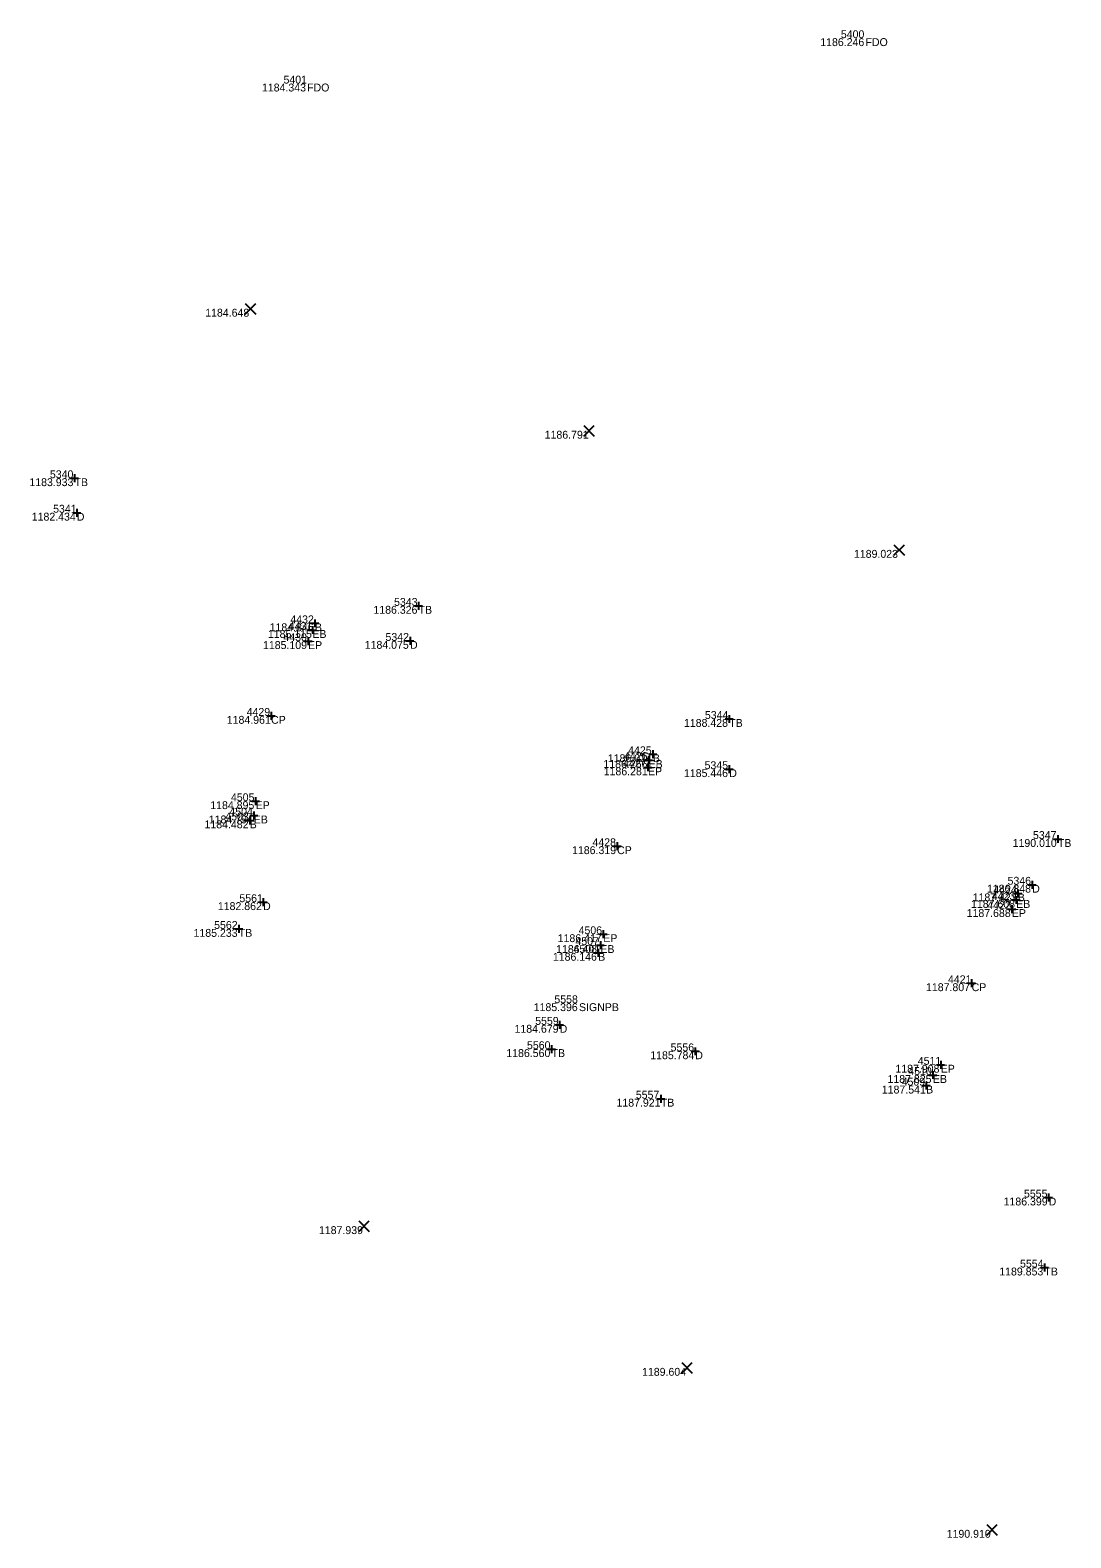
# Model space of a CAD drawing. Extents: x 2044997 to 2050342, y 455233 to 458054.
# Drawn here: x 2047059.7 to 2047191.5, y 457097.5 to 457288.5 of the extents above; entities that cross this region are included whole.
import ezdxf

# ---------------------------------------------------------------- set-up
doc = ezdxf.new("R2010")
doc.units = 0
for name, color, linetype in [('SV_X_Random_Point', 7, 'Continuous'), ('SV_X_Shot_Marker', 7, 'Continuous'), ('SV_X_Text_Comment', 7, 'Continuous'), ('SV_X_Text_Elevation', 7, 'Continuous'), ('SV_X_Text_Name', 7, 'Continuous')]:
    doc.layers.add(name, color=color, linetype=linetype)

msp = doc.modelspace()

# ---------------------------------------------------------------- linework, layer by layer
at = {"layer": 'SV_X_Random_Point'}
for p, q in [((2047086.91, 457252.54), (2047088.24, 457253.87)), ((2047086.91, 457253.87), (2047088.24, 457252.54)), ((2047129.8, 457237.08), (2047131.13, 457238.42)), ((2047129.8, 457238.42), (2047131.13, 457237.08)), ((2047169.1, 457221.99), (2047170.43, 457223.32)), ((2047169.1, 457223.32), (2047170.43, 457221.99)), ((2047101.3, 457136.31), (2047102.63, 457137.65)), ((2047101.3, 457137.65), (2047102.63, 457136.31)), ((2047142.23, 457118.36), (2047143.56, 457119.7)), ((2047142.23, 457119.7), (2047143.56, 457118.36)), ((2047180.86, 457097.84), (2047182.19, 457099.18)), ((2047180.86, 457099.18), (2047182.19, 457097.84))]:
    msp.add_line(p, q, dxfattribs=at)
at = {"layer": 'SV_X_Shot_Marker'}
for p, q in [((2047065.28, 457232.24), (2047065.28, 457231.24)), ((2047064.78, 457231.74), (2047065.78, 457231.74)), ((2047065.28, 457231.74), (2047065.28, 457231.74)), ((2047065.07, 457227.37), (2047066.07, 457227.37)), ((2047065.57, 457227.87), (2047065.57, 457226.87)), ((2047065.57, 457227.37), (2047065.57, 457227.37)), ((2047108.38, 457215.57), (2047109.38, 457215.57)), ((2047108.88, 457216.07), (2047108.88, 457215.07)), ((2047108.88, 457215.57), (2047108.88, 457215.57)), ((2047095.24, 457213.36), (2047096.24, 457213.36)), ((2047095.42, 457213.01), (2047095.42, 457212.01)), ((2047095.74, 457213.86), (2047095.74, 457212.86)), ((2047095.74, 457213.36), (2047095.74, 457213.36)), ((2047094.37, 457211.1), (2047095.37, 457211.1)), ((2047094.87, 457211.6), (2047094.87, 457210.6)), ((2047094.87, 457211.1), (2047094.87, 457211.1)), ((2047094.92, 457212.51), (2047095.92, 457212.51)), ((2047095.42, 457212.51), (2047095.42, 457212.51)), ((2047107.29, 457211.13), (2047108.29, 457211.13)), ((2047107.79, 457211.63), (2047107.79, 457210.63)), ((2047107.79, 457211.13), (2047107.79, 457211.13)), ((2047089.69, 457201.63), (2047090.69, 457201.63)), ((2047090.19, 457202.13), (2047090.19, 457201.13)), ((2047090.19, 457201.63), (2047090.19, 457201.63)), ((2047147.74, 457201.24), (2047148.74, 457201.24)), ((2047148.24, 457201.74), (2047148.24, 457200.74)), ((2047148.24, 457201.24), (2047148.24, 457201.24)), ((2047137.52, 457196.04), (2047138.52, 457196.04)), ((2047137.94, 457195.61), (2047137.94, 457194.61)), ((2047138.02, 457196.54), (2047138.02, 457195.54)), ((2047138.02, 457196.04), (2047138.02, 457196.04)), ((2047138.06, 457196.77), (2047139.06, 457196.77)), ((2047138.56, 457197.27), (2047138.56, 457196.27)), ((2047138.56, 457196.77), (2047138.56, 457196.77)), ((2047137.44, 457195.11), (2047138.44, 457195.11)), ((2047137.94, 457195.11), (2047137.94, 457195.11)), ((2047147.74, 457194.88), (2047148.74, 457194.88)), ((2047148.24, 457195.38), (2047148.24, 457194.38)), ((2047148.24, 457194.88), (2047148.24, 457194.88)), ((2047087.73, 457190.82), (2047088.73, 457190.82)), ((2047088.23, 457191.32), (2047088.23, 457190.32)), ((2047088.23, 457190.82), (2047088.23, 457190.82)), ((2047086.98, 457188.39), (2047087.98, 457188.39)), ((2047087.48, 457188.89), (2047087.48, 457187.89)), ((2047087.48, 457188.39), (2047087.48, 457188.39)), ((2047087.49, 457189.01), (2047088.49, 457189.01)), ((2047087.99, 457189.51), (2047087.99, 457188.51)), ((2047087.99, 457189.01), (2047087.99, 457189.01)), ((2047189.38, 457186.03), (2047190.38, 457186.03)), ((2047189.88, 457186.53), (2047189.88, 457185.53)), ((2047189.88, 457186.03), (2047189.88, 457186.03)), ((2047133.53, 457185.12), (2047134.53, 457185.12)), ((2047134.03, 457185.62), (2047134.03, 457184.62)), ((2047134.03, 457185.12), (2047134.03, 457185.12)), ((2047186.12, 457180.24), (2047187.12, 457180.24)), ((2047186.62, 457180.74), (2047186.62, 457179.74)), ((2047186.62, 457180.24), (2047186.62, 457180.24)), ((2047089.17, 457178.53), (2047089.17, 457177.53)), ((2047184.3, 457179.14), (2047185.3, 457179.14)), ((2047184.6, 457178.81), (2047184.6, 457177.81)), ((2047184.8, 457179.64), (2047184.8, 457178.64)), ((2047184.8, 457179.14), (2047184.8, 457179.14)), ((2047088.67, 457178.03), (2047089.67, 457178.03)), ((2047089.17, 457178.03), (2047089.17, 457178.03)), ((2047183.55, 457177.15), (2047184.55, 457177.15)), ((2047184.05, 457177.65), (2047184.05, 457176.65)), ((2047184.05, 457177.15), (2047184.05, 457177.15)), ((2047184.1, 457178.31), (2047185.1, 457178.31)), ((2047184.6, 457178.31), (2047184.6, 457178.31)), ((2047085.59, 457174.64), (2047086.59, 457174.64)), ((2047086.09, 457175.14), (2047086.09, 457174.14)), ((2047086.09, 457174.64), (2047086.09, 457174.64)), ((2047131.41, 457172.59), (2047132.41, 457172.59)), ((2047131.78, 457173.97), (2047132.78, 457173.97)), ((2047131.91, 457173.09), (2047131.91, 457172.09)), ((2047131.91, 457172.59), (2047131.91, 457172.59)), ((2047132.28, 457174.47), (2047132.28, 457173.47)), ((2047132.28, 457173.97), (2047132.28, 457173.97)), ((2047131.13, 457171.61), (2047132.13, 457171.61)), ((2047131.63, 457172.11), (2047131.63, 457171.11)), ((2047131.63, 457171.61), (2047131.63, 457171.61)), ((2047178.45, 457167.76), (2047179.45, 457167.76)), ((2047178.95, 457168.26), (2047178.95, 457167.26)), ((2047178.95, 457167.76), (2047178.95, 457167.76)), ((2047126.25, 457162.49), (2047127.25, 457162.49)), ((2047126.75, 457162.99), (2047126.75, 457161.99)), ((2047126.75, 457162.49), (2047126.75, 457162.49)), ((2047125.23, 457159.41), (2047126.23, 457159.41)), ((2047125.73, 457159.91), (2047125.73, 457158.91)), ((2047125.73, 457159.41), (2047125.73, 457159.41)), ((2047143.93, 457159.64), (2047143.93, 457158.64)), ((2047143.43, 457159.14), (2047144.43, 457159.14)), ((2047143.93, 457159.14), (2047143.93, 457159.14)), ((2047174.53, 457157.43), (2047175.53, 457157.43)), ((2047175.03, 457157.93), (2047175.03, 457156.93)), ((2047175.03, 457157.43), (2047175.03, 457157.43)), ((2047173.54, 457156.13), (2047174.54, 457156.13)), ((2047174.04, 457156.63), (2047174.04, 457155.63)), ((2047174.04, 457156.13), (2047174.04, 457156.13)), ((2047139.57, 457153.63), (2047139.57, 457152.63)), ((2047172.68, 457154.79), (2047173.68, 457154.79)), ((2047173.18, 457155.29), (2047173.18, 457154.29)), ((2047173.18, 457154.79), (2047173.18, 457154.79)), ((2047139.07, 457153.13), (2047140.07, 457153.13)), ((2047139.57, 457153.13), (2047139.57, 457153.13)), ((2047188.21, 457140.61), (2047189.21, 457140.61)), ((2047188.71, 457141.11), (2047188.71, 457140.11)), ((2047188.71, 457140.61), (2047188.71, 457140.61)), ((2047187.67, 457131.74), (2047188.67, 457131.74)), ((2047188.17, 457132.24), (2047188.17, 457131.24)), ((2047188.17, 457131.74), (2047188.17, 457131.74))]:
    msp.add_line(p, q, dxfattribs=at)

# ---------------------------------------------------------------- texts
at = {"layer": 'SV_X_Text_Comment'}
for s, p in [('FDO', (2047165.5, 457286.49)), ('FDO', (2047094.75, 457280.74)), ('TB', (2047065.28, 457230.74)), ('D', (2047065.57, 457226.37)), ('TB', (2047108.88, 457214.57)), ('B', (2047095.74, 457212.36)), ('EP', (2047094.87, 457210.1)), ('EB', (2047095.42, 457211.51)), ('D', (2047107.79, 457210.13)), ('CP', (2047090.19, 457200.63)), ('TB', (2047148.24, 457200.24)), ('EB', (2047138.02, 457195.04)), ('B', (2047138.56, 457195.77)), ('EP', (2047137.94, 457194.11)), ('D', (2047148.24, 457193.88)), ('EP', (2047088.23, 457189.82)), ('B', (2047087.48, 457187.39)), ('EB', (2047087.99, 457188.01)), ('TB', (2047189.88, 457185.03)), ('CP', (2047134.03, 457184.12)), ('D', (2047186.62, 457179.24)), ('B', (2047184.8, 457178.14)), ('D', (2047089.17, 457177.03)), ('EP', (2047184.05, 457176.15)), ('EB', (2047184.6, 457177.31)), ('TB', (2047086.09, 457173.64)), ('EB', (2047131.91, 457171.59)), ('EP', (2047132.28, 457172.97)), ('B', (2047131.63, 457170.61)), ('CP', (2047178.95, 457166.76)), ('SIGNPB', (2047129.2, 457164.23)), ('D', (2047126.75, 457161.49)), ('TB', (2047125.73, 457158.41)), ('D', (2047143.93, 457158.14)), ('EP', (2047175.03, 457156.43)), ('EB', (2047174.04, 457155.13)), ('B', (2047173.18, 457153.79)), ('TB', (2047139.57, 457152.13)), ('D', (2047188.71, 457139.61)), ('TB', (2047188.17, 457130.74))]:
    msp.add_text(s, height=1, dxfattribs=at).set_placement(p)
at = {"layer": 'SV_X_Text_Elevation'}
for s, p in [('1186.246', (2047159.77, 457286.49)), ('1184.343', (2047089.03, 457280.74)), ('1184.648', (2047081.84, 457252.21)), ('1186.791', (2047124.85, 457236.75)), ('1183.933', (2047059.56, 457230.74)), ('1182.434', (2047059.86, 457226.37)), ('1189.023', (2047164.04, 457221.66)), ('1186.326', (2047103.15, 457214.57)), ('1184.846', (2047090, 457212.36)), ('1185.109', (2047089.16, 457210.1)), ('1185.115', (2047089.78, 457211.51)), ('1184.075', (2047102.05, 457210.13)), ('1184.961', (2047084.57, 457200.63)), ('1188.428', (2047142.5, 457200.24)), ('1186.266', (2047132.29, 457195.04)), ('1186.034', (2047132.85, 457195.77)), ('1186.281', (2047132.33, 457194.11)), ('1185.446', (2047142.5, 457193.88)), ('1184.895', (2047082.48, 457189.82)), ('1184.482', (2047081.75, 457187.39)), ('1184.794', (2047082.29, 457188.01)), ('1190.010', (2047184.15, 457185.03)), ('1186.319', (2047128.32, 457184.12)), ('1186.848', (2047180.89, 457179.24)), ('1187.608', (2047178.87, 457177.31)), ('1187.423', (2047179.08, 457178.14)), ('1182.862', (2047083.44, 457177.03)), ('1187.688', (2047178.32, 457176.15)), ('1185.233', (2047080.36, 457173.64)), ('1186.401', (2047126.3, 457171.59)), ('1186.417', (2047126.5, 457172.97)), ('1186.146', (2047125.89, 457170.61)), ('1187.807', (2047173.17, 457166.76)), ('1185.396', (2047123.46, 457164.23)), ('1184.679', (2047121.03, 457161.49)), ('1186.560', (2047119.99, 457158.41)), ('1185.784', (2047138.23, 457158.14)), ('1187.908', (2047169.29, 457156.43)), ('1187.825', (2047168.29, 457155.13)), ('1187.541', (2047167.57, 457153.79)), ('1187.921', (2047133.95, 457152.13)), ('1186.399', (2047183, 457139.61)), ('1187.939', (2047096.25, 457135.98)), ('1189.853', (2047182.45, 457130.74)), ('1189.604', (2047137.19, 457118.03)), ('1190.910', (2047175.79, 457097.51))]:
    msp.add_text(s, height=1, dxfattribs=at).set_placement(p)
at = {"layer": 'SV_X_Text_Name'}
for s, p in [('5400', (2047162.38, 457287.49)), ('5401', (2047091.76, 457281.74)), ('5340', (2047062.16, 457231.74)), ('5341', (2047062.57, 457227.37)), ('5343', (2047105.77, 457215.57)), ('4431', (2047092.43, 457212.51)), ('4432', (2047092.63, 457213.36)), ('4430', (2047091.75, 457211.1)), ('5342', (2047104.68, 457211.13)), ('4429', (2047087.09, 457201.63)), ('5344', (2047145.15, 457201.24)), ('4425', (2047135.43, 457196.77)), ('4427', (2047134.78, 457195.11)), ('4426', (2047134.9, 457196.04)), ('5345', (2047145.11, 457194.88)), ('4505', (2047085.1, 457190.82)), ('4504', (2047084.9, 457189.01)), ('4503', (2047084.38, 457188.39)), ('4428', (2047130.91, 457185.12)), ('5347', (2047186.72, 457186.03)), ('5346', (2047183.5, 457180.24)), ('5561', (2047086.17, 457178.03)), ('4423', (2047181.5, 457178.31)), ('4424', (2047181.71, 457179.14)), ('4422', (2047180.93, 457177.15)), ('5562', (2047082.97, 457174.64)), ('4506', (2047129.15, 457173.97)), ('4508', (2047128.51, 457171.61)), ('4507', (2047128.75, 457172.59)), ('4421', (2047175.95, 457167.76)), ('5558', (2047126.08, 457165.23)), ('5559', (2047123.65, 457162.49)), ('5560', (2047122.61, 457159.41)), ('5556', (2047140.81, 457159.14)), ('4511', (2047172.13, 457157.43)), ('4509', (2047170.08, 457154.79)), ('4510', (2047170.92, 457156.13)), ('5557', (2047136.4, 457153.13)), ('5555', (2047185.58, 457140.61)), ('5554', (2047185.08, 457131.74))]:
    msp.add_text(s, height=1, dxfattribs=at).set_placement(p)

doc.saveas('drawing.dxf')
